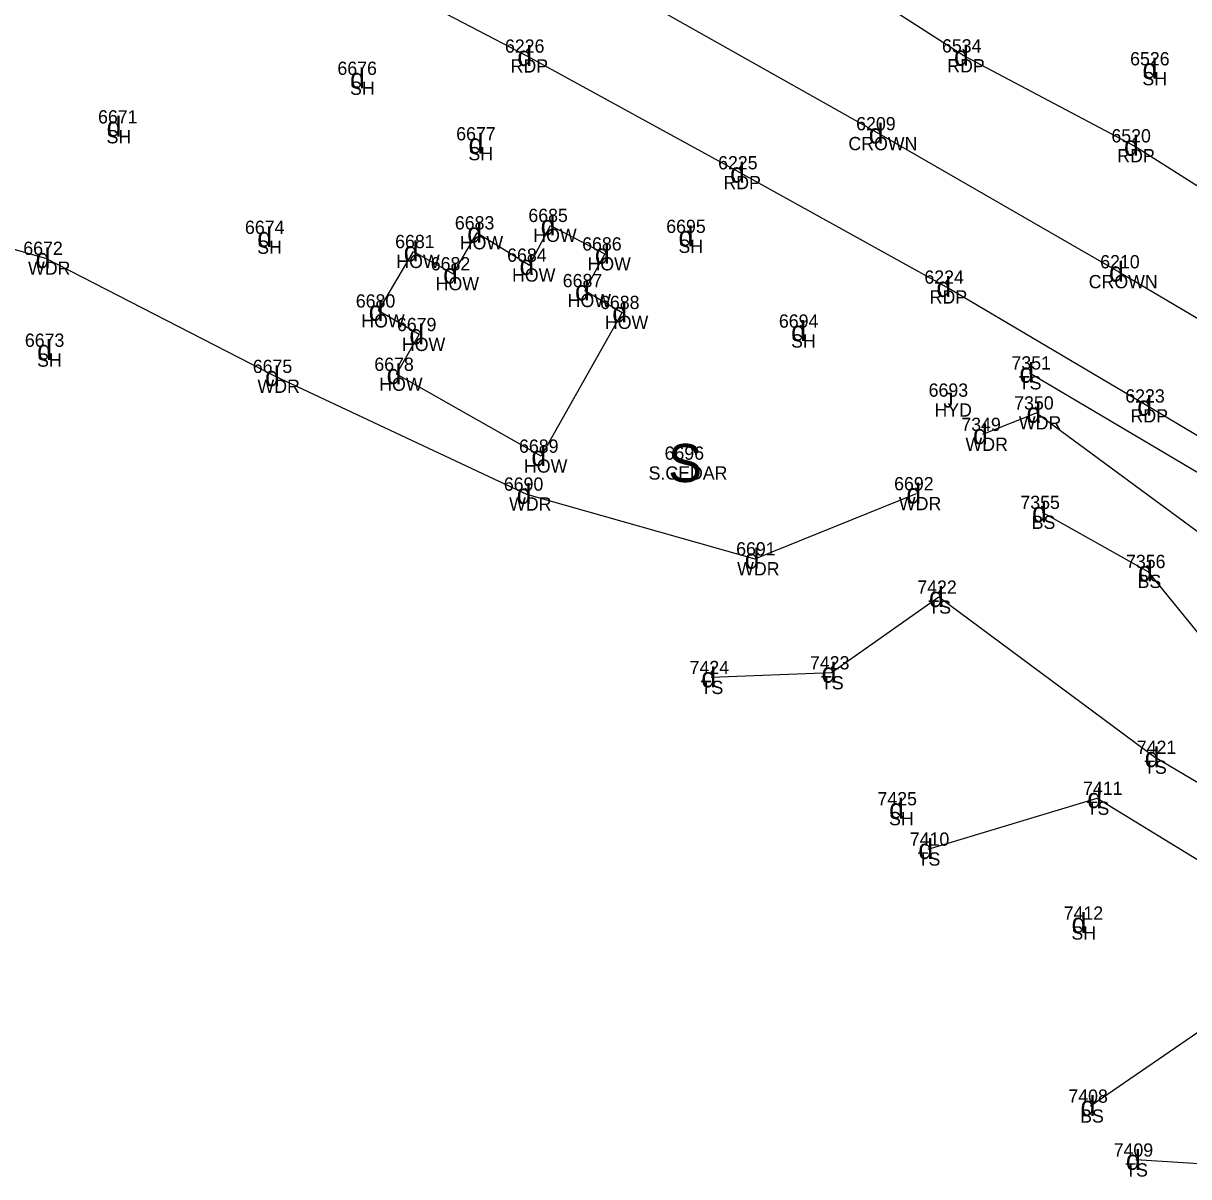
# Model space of a CAD drawing. Extents: x 69415 to 80913, y 7576 to 15059.
# Drawn here: x 75742.7 to 75918.4, y 14213.4 to 14387.3 of the extents above; entities that cross this region are included whole.
import ezdxf

# ---------------------------------------------------------------- set-up
doc = ezdxf.new("R2010")
doc.units = 0
for name, color, linetype in [('Level 11', 7, 'Continuous'), ('Level 13', 7, 'Continuous'), ('Level 14', 7, 'Continuous'), ('Level 15', 7, 'Continuous'), ('Level 46', 7, 'Continuous'), ('Level 47', 7, 'Continuous'), ('Level 48', 7, 'Continuous')]:
    doc.layers.add(name, color=color, linetype=linetype)

msp = doc.modelspace()

# ---------------------------------------------------------------- linework, layer by layer
at = {"layer": 'Level 11'}
for p, q in [((75884.51, 14382.36), (75852.91, 14402.67)), ((75818.7, 14382.33), (75786.48, 14399.11)), ((75850.77, 14364.74), (75818.7, 14382.33)), ((75910.13, 14368.8), (75884.51, 14382.36)), ((75942.47, 14348.18), (75910.13, 14368.8)), ((75881.86, 14347.5), (75850.77, 14364.74)), ((75912.13, 14329.58), (75881.86, 14347.5)), ((75941.97, 14311.75), (75912.13, 14329.58))]:
    msp.add_line(p, q, dxfattribs=at)
at = {"layer": 'Level 13'}
for p, q in [((75819.02, 14350.81), (75822.21, 14356.8)), ((75822.21, 14356.8), (75830.38, 14352.5)), ((75807.51, 14349.51), (75811.14, 14355.68)), ((75811.14, 14355.68), (75819.02, 14350.81)), ((75796.29, 14343.9), (75801.57, 14352.86)), ((75801.57, 14352.86), (75807.51, 14349.51)), ((75830.38, 14352.5), (75827.39, 14346.97)), ((75827.39, 14346.97), (75833.01, 14343.68)), ((75802.41, 14340.35), (75796.29, 14343.9)), ((75833.01, 14343.68), (75820.81, 14322.01)), ((75798.99, 14334.35), (75802.41, 14340.35)), ((75820.81, 14322.01), (75798.99, 14334.35))]:
    msp.add_line(p, q, dxfattribs=at)
at = {"layer": 'Level 14'}
for p, q in [((75701.87, 14364.36), (75746.08, 14351.84)), ((75746.08, 14351.84), (75780.67, 14334.04)), ((75780.67, 14334.04), (75818.6, 14316.29)), ((75887.38, 14325.29), (75895.44, 14328.52)), ((75895.44, 14328.52), (75928.35, 14304.25)), ((75818.6, 14316.29), (75852.97, 14306.52)), ((75852.97, 14306.52), (75877.34, 14316.35))]:
    msp.add_line(p, q, dxfattribs=at)
at = {"layer": 'Level 48'}
for p, q in [((75835.73, 14390.93), (75871.66, 14370.63)), ((75871.66, 14370.63), (75907.88, 14349.81)), ((75907.88, 14349.81), (75943.4, 14328.7)), ((75894.37, 14334.56), (75932.26, 14312.11)), ((75896.28, 14313.53), (75912.25, 14304.62)), ((75912.25, 14304.62), (75927.99, 14285.18)), ((75880.74, 14300.75), (75864.56, 14289.34)), ((75913.26, 14276.6), (75880.74, 14300.75)), ((75864.56, 14289.34), (75846.42, 14288.63)), ((75938.39, 14261.7), (75913.26, 14276.6)), ((75879.13, 14262.76), (75904.6, 14270.42)), ((75904.6, 14270.42), (75932.1, 14253.6)), ((75924.75, 14238.55), (75903.59, 14224.01)), ((75946.63, 14213.6), (75910.42, 14215.88))]:
    msp.add_line(p, q, dxfattribs=at)

# ---------------------------------------------------------------- texts
at = {"layer": 'Level 14'}
msp.add_text('S', height=5.75, dxfattribs=at).set_placement((75839.92, 14318.09))
at = {"layer": 'Level 15'}
msp.add_text('J', height=2.26, dxfattribs=at).set_placement((75881.42, 14329.33))
at = {"layer": 'Level 46'}
for s, p in [('6226', (75815.33, 14382.83)), ('6534', (75881.2, 14382.86)), ('6526', (75909.56, 14380.92)), ('6676', (75790.08, 14379.48)), ('RDP', (75816.18, 14379.83)), ('RDP', (75882, 14379.86)), ('SH', (75911.41, 14377.92)), ('SH', (75791.98, 14376.48)), ('6671', (75754, 14372.16)), ('6209', (75868.27, 14371.13)), ('SH', (75755.28, 14369.16)), ('6677', (75807.98, 14369.61)), ('6520', (75906.74, 14369.3)), ('CROWN', (75867.1, 14368.13)), ('SH', (75809.83, 14366.61)), ('6225', (75847.46, 14365.24)), ('RDP', (75907.62, 14366.3)), ('RDP', (75848.26, 14362.24)), ('6685', (75818.86, 14357.3)), ('6674', (75776.14, 14355.51)), ('6683', (75807.78, 14356.18)), ('6695', (75839.64, 14355.65)), ('6681', (75798.78, 14353.36)), ('HOW', (75808.52, 14353.18)), ('HOW', (75819.6, 14354.3)), ('6686', (75826.97, 14353)), ('6672', (75742.73, 14352.34)), ('SH', (75777.99, 14352.51)), ('6684', (75815.66, 14351.31)), ('SH', (75841.48, 14352.65)), ('WDR', (75743.45, 14349.34)), ('HOW', (75798.96, 14350.36)), ('6682', (75804.15, 14350.01)), ('HOW', (75827.77, 14350)), ('6210', (75905.05, 14350.31)), ('HOW', (75816.4, 14348.31)), ('6687', (75824.04, 14347.47)), ('6224', (75878.55, 14348)), ('HOW', (75804.89, 14347.01)), ('CROWN', (75903.32, 14347.31)), ('6680', (75792.85, 14344.4)), ('HOW', (75824.78, 14344.47)), ('6688', (75829.66, 14344.18)), ('RDP', (75879.35, 14345)), ('HOW', (75793.68, 14341.4)), ('6679', (75799.05, 14340.85)), ('HOW', (75830.4, 14341.18)), ('6694', (75856.62, 14341.37)), ('6673', (75742.97, 14338.48)), ('HOW', (75799.8, 14337.85)), ('SH', (75858.46, 14338.37)), ('SH', (75744.81, 14335.48)), ('6675', (75777.32, 14334.54)), ('6678', (75795.64, 14334.85)), ('7351', (75891.68, 14335.06)), ('HOW', (75796.38, 14331.85)), ('TS', (75892.78, 14332.06)), ('WDR', (75778.03, 14331.54)), ('6693', (75879.19, 14330.96)), ('6223', (75908.83, 14330.08)), ('7350', (75892.09, 14329.02)), ('HYD', (75880.07, 14327.96)), ('RDP', (75909.62, 14327.08)), ('7349', (75884.12, 14325.79)), ('WDR', (75892.8, 14326.02)), ('6689', (75817.45, 14322.51)), ('6696', (75839.39, 14321.46)), ('WDR', (75884.75, 14322.79)), ('HOW', (75818.2, 14319.51)), ('S.CEDAR', (75836.98, 14318.46)), ('6690', (75815.16, 14316.79)), ('6692', (75873.99, 14316.85)), ('WDR', (75815.96, 14313.79)), ('WDR', (75874.71, 14313.85)), ('7355', (75893.02, 14314.03)), ('BS', (75894.72, 14311.03)), ('6691', (75850.18, 14307.02)), ('WDR', (75850.33, 14304.02)), ('7356', (75908.94, 14305.12)), ('BS', (75910.69, 14302.12)), ('7422', (75877.48, 14301.25)), ('TS', (75879.15, 14298.25)), ('7423', (75861.3, 14289.84)), ('7424', (75843.16, 14289.13)), ('TS', (75844.83, 14286.13)), ('TS', (75862.97, 14286.84)), ('7421', (75910.57, 14277.1)), ('TS', (75911.67, 14274.1)), ('7411', (75902.47, 14270.92)), ('7425', (75871.48, 14269.35)), ('TS', (75903.01, 14267.92)), ('SH', (75873.23, 14266.35)), ('7410', (75876.35, 14263.26)), ('TS', (75877.54, 14260.26)), ('7412', (75899.54, 14252.1)), ('SH', (75900.72, 14249.1)), ('7408', (75900.25, 14224.51)), ('BS', (75902.03, 14221.51)), ('7409', (75907.08, 14216.38)), ('TS', (75908.83, 14213.38))]:
    msp.add_text(s, height=2, dxfattribs=at).set_placement(p)
at = {"layer": 'Level 47'}
for p in [(75817.2, 14380.83), (75883.01, 14380.86), (75911.43, 14378.92), (75791.99, 14377.48), (75755.29, 14370.16), (75809.84, 14367.61), (75870.16, 14369.13), (75908.63, 14367.3), (75849.27, 14363.24), (75820.71, 14355.3), (75778, 14353.51), (75809.64, 14354.18), (75841.49, 14353.65), (75744.58, 14350.34), (75800.07, 14351.36), (75828.88, 14351), (75817.52, 14349.31), (75906.38, 14348.31), (75806.01, 14348.01), (75825.89, 14345.47), (75880.36, 14346), (75794.79, 14342.4), (75831.51, 14342.18), (75858.47, 14339.37), (75800.91, 14338.85), (75744.82, 14336.48), (75779.17, 14332.54), (75797.49, 14332.85), (75892.87, 14333.06), (75893.94, 14327.02), (75910.63, 14328.08), (75885.88, 14323.79), (75819.31, 14320.51), (75817.1, 14314.79), (75875.84, 14314.85), (75894.78, 14312.03), (75851.47, 14305.02), (75910.75, 14303.12), (75879.24, 14299.25), (75844.92, 14287.13), (75863.06, 14287.84), (75911.76, 14275.1), (75873.24, 14267.35), (75903.1, 14268.92), (75877.63, 14261.26), (75900.73, 14250.1), (75902.09, 14222.51), (75908.92, 14214.38)]:
    msp.add_text('d', height=3, dxfattribs=at).set_placement(p)

doc.saveas('drawing.dxf')
